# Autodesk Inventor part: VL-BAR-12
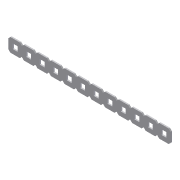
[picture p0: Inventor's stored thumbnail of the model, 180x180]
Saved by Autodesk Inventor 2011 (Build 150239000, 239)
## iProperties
Created: 2005-08
Part Number: VL-BAR-12
Document SubType Name: Sheet Metal
Density: 1 g/cm^3
Mass: 2.02888 g
Surface Area: 39.3158 cm^2
Volume: 2.02888 cm^3
Sheet Metal Rule: Default
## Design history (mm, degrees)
node "Face1"
  sketch "Sketch1"
    geometry: L1 (-15.07, 9.738)-(-23.96, 9.738); L2 (-25.865, 7.833)-(-25.865, -1.057); L3 (-23.96, -2.962)-(-15.07, -2.962); L4 (-13.165, -1.057)-(-13.165, 7.833); L5 (-25.865, 7.833)-(-23.96, 9.738); L6 (-25.865, -1.057)-(-23.96, -2.962); L7 (-15.07, -2.962)-(-13.165, -1.057); L8 (-13.165, 7.833)-(-15.07, 9.738); L9 (-21.801, 5.674)-(-17.229, 5.674); L10 (-17.229, 5.674)-(-17.229, 1.102); L11 (-17.229, 1.102)-(-21.801, 1.102); L12 (-21.801, 1.102)-(-21.801, 5.674); 4 further points
    constraints: 24 end point, 8 point on line, 4 parallel, 2 horizontal, 2 perpendicular
    dimensions: "d0" = 12.7 distance of point (-25.865, 9.738) point (-25.865, -2.962); "d1" = 12.7 distance of point (-13.165, 9.738) point (-25.865, 9.738); "d2" = 1.905 distance of L2.start point (-25.865, 9.738); "d3" = 1.905 distance of L1.end point (-25.865, 9.738) (= d2); "d4" = 1.905 distance of L2.end point (-25.865, -2.962) (= d2); "d5" = 1.905 distance of L3.start point (-25.865, -2.962) (= d4); "d6" = 1.905 distance of L3.end point (-13.165, -2.962) (= d2); "d7" = 1.905 distance of L4.start point (-13.165, -2.962) (= d6); "d8" = 1.905 distance of L4.end point (-13.165, 9.738) (= d2); "d9" = 1.905 distance of L1.start point (-13.165, 9.738) (= d8); "d10" = 4.572 distance of L11.end L9.start; "d11" = 4.572 distance of L10.end L11.end; "d12" = 4.064 distance between parallel lines of L1 L9; "d13" = 4.064 distance between parallel lines of L4 L10
pattern_linear "Rectangular Pattern1" dims "d17" = 12.7
sketch "Sketch2"
  geometry: L1 (121.031, -4.064)-(121.031, -8.636) reference; L2 (121.031, -8.636)-(116.459, -8.636) reference; L3 (116.459, -8.636)-(116.459, -4.064) reference; L4 (116.459, -4.064)-(121.031, -4.064) reference; L5 (108.331, -4.064)-(108.331, -8.636) reference; L6 (108.331, -8.636)-(103.759, -8.636) reference; L7 (103.759, -8.636)-(103.759, -4.064) reference; L8 (103.759, -4.064)-(108.331, -4.064) reference; L9 (95.631, -4.064)-(95.631, -8.636) reference; L10 (95.631, -8.636)-(91.059, -8.636) reference; L11 (91.059, -8.636)-(91.059, -4.064) reference; L12 (91.059, -4.064)-(95.631, -4.064) reference; L13 (82.931, -4.064)-(82.931, -8.636) reference; L14 (82.931, -8.636)-(78.359, -8.636) reference; L15 (78.359, -8.636)-(78.359, -4.064) reference; L16 (78.359, -4.064)-(82.931, -4.064) reference; L17 (70.231, -4.064)-(70.231, -8.636) reference; L18 (70.231, -8.636)-(65.659, -8.636) reference; L19 (65.659, -8.636)-(65.659, -4.064) reference; L20 (65.659, -4.064)-(70.231, -4.064) reference; L21 (57.531, -4.064)-(57.531, -8.636) reference; L22 (57.531, -8.636)-(52.959, -8.636) reference; L23 (52.959, -8.636)-(52.959, -4.064) reference; L24 (52.959, -4.064)-(57.531, -4.064) reference; L25 (44.831, -4.064)-(44.831, -8.636) reference; L26 (44.831, -8.636)-(40.259, -8.636) reference; L27 (40.259, -8.636)-(40.259, -4.064) reference; L28 (40.259, -4.064)-(44.831, -4.064) reference; L29 (32.131, -4.064)-(32.131, -8.636) reference; L30 (32.131, -8.636)-(27.559, -8.636) reference; L31 (27.559, -8.636)-(27.559, -4.064) reference; L32 (27.559, -4.064)-(32.131, -4.064) reference; L33 (19.431, -4.064)-(19.431, -8.636) reference; L34 (19.431, -8.636)-(14.859, -8.636) reference; L35 (14.859, -8.636)-(14.859, -4.064) reference; L36 (14.859, -4.064)-(19.431, -4.064) reference; L37 (6.731, -4.064)-(6.731, -8.636) reference; L38 (6.731, -8.636)-(2.159, -8.636) reference; L39 (2.159, -8.636)-(2.159, -4.064) reference; L40 (2.159, -4.064)-(6.731, -4.064) reference; L41 (0, 0)-(8.89, 0) reference; L42 (-1.905, -1.905)-(0, 0) reference; L43 (-1.905, -10.795)-(-1.905, -1.905) reference; L44 (0, -12.7)-(-1.905, -10.795) reference; L45 (8.89, -12.7)-(0, -12.7) reference; L46 (10.795, -10.795)-(8.89, -12.7) reference; L47 (12.7, -12.7)-(10.795, -10.795) reference; L48 (21.59, -12.7)-(12.7, -12.7) reference; L49 (23.495, -10.795)-(21.59, -12.7) reference; L50 (25.4, -12.7)-(23.495, -10.795) reference; L51 (34.29, -12.7)-(25.4, -12.7) reference; L52 (36.195, -10.795)-(34.29, -12.7) reference; L53 (38.1, -12.7)-(36.195, -10.795) reference; L54 (46.99, -12.7)-(38.1, -12.7) reference; L55 (48.895, -10.795)-(46.99, -12.7) reference; L56 (50.8, -12.7)-(48.895, -10.795) reference; L57 (59.69, -12.7)-(50.8, -12.7) reference; L58 (61.595, -10.795)-(59.69, -12.7) reference; L59 (63.5, -12.7)-(61.595, -10.795) reference; L60 (72.39, -12.7)-(63.5, -12.7) reference; L61 (74.295, -10.795)-(72.39, -12.7) reference; L62 (76.2, -12.7)-(74.295, -10.795) reference; L63 (85.09, -12.7)-(76.2, -12.7) reference; L64 (86.995, -10.795)-(85.09, -12.7) reference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; C1 r 2.286 at (4.445, -6.35); C2 r 2.286 at (144.145, -6.35)
  constraints: 7 tangent, 2 centre point
  node "Projected Loop1"
body "Solid1"
face "Plate1" dims "Thickness" = 1.27
other parameters: "BendRadius" = 1.27 (= Thickness), "BendReliefWidth" = 1.27 (= Thickness), "BendReliefDepth" = 0.635 (= 0.5 x Thickness), "CornerReliefSize" = 5.08 (= 4 x Thickness), "SeamGap" = 0.00508, "MinimumRemnant" = 2.54 (= 2 x Thickness), "TransitionRadius" = 1.27 (= BendRadius), "d14" = 1.27 (= BendRadius), "JacobiRadiusSize" = 1.27 (= Thickness), "GapSize" = 1.27 (= Thickness)
